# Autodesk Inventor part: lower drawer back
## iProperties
Created: 2005-05
Part Number: lower drawer back
Material: mdf
Document SubType Name: Modeling
Designer: a.campbell
Manufacturer: Standard
Standards Organization: Custom
Author: a.campbell
Comments: machine to detail
length: 278
thickness: 12
width: 245
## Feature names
1. Extrusion1
